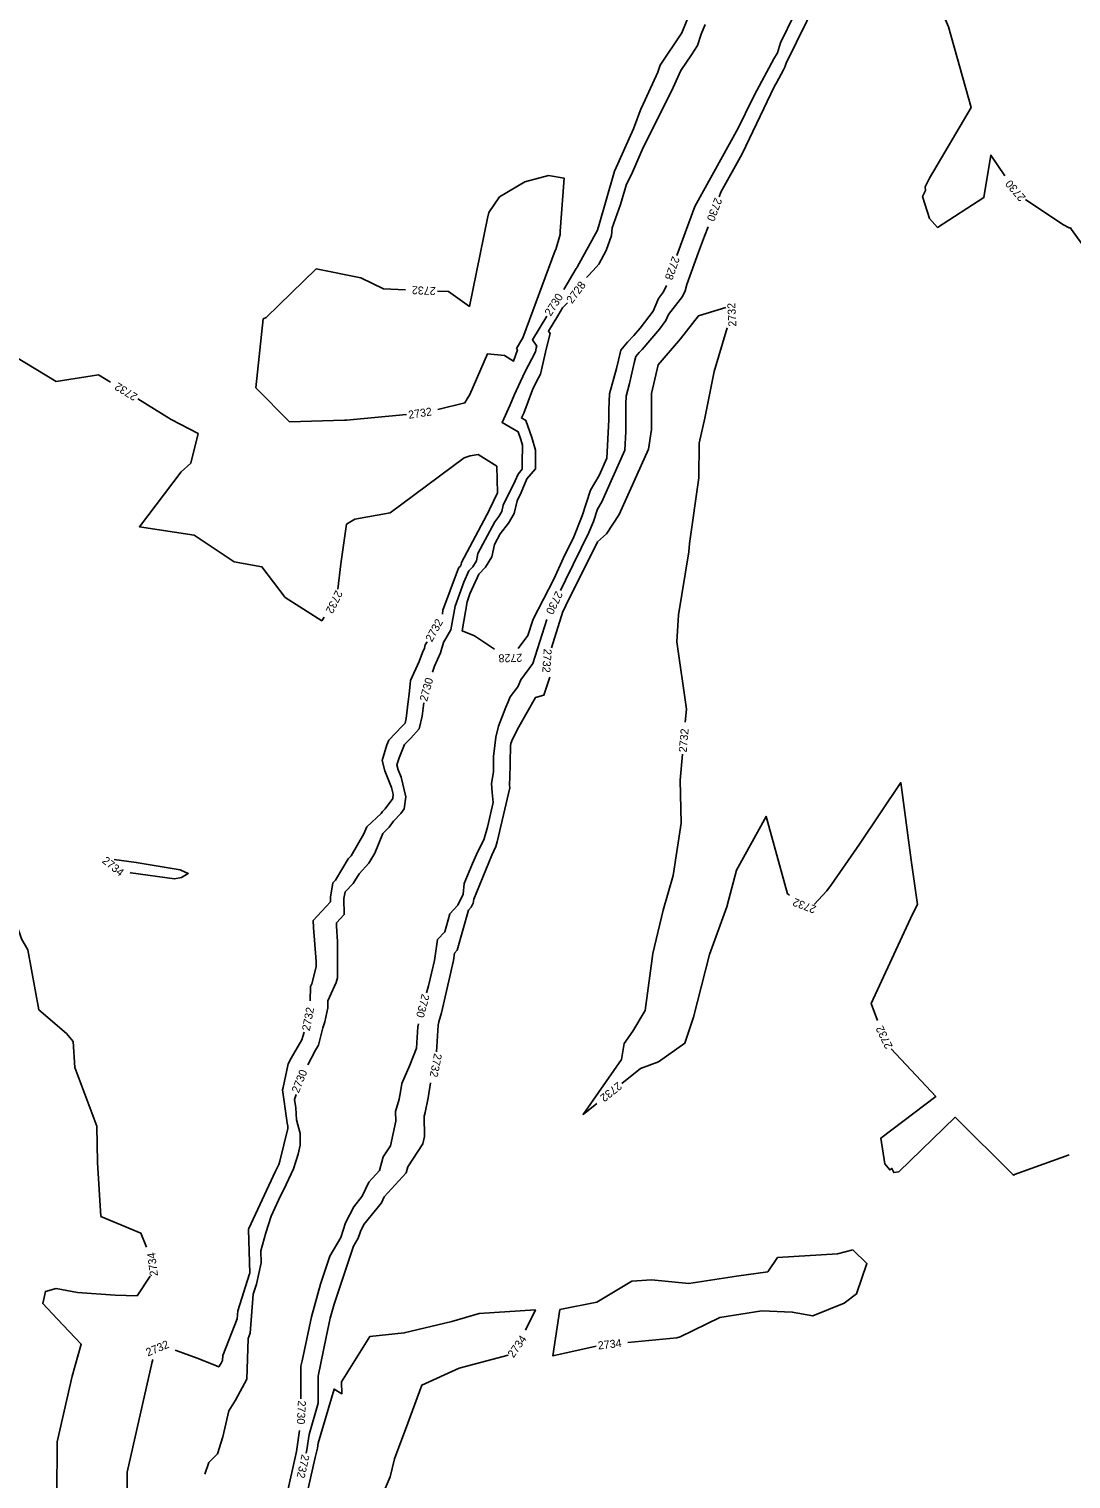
# Model space of a CAD drawing. Extents: x 1326424 to 1329294, y 1001359 to 1003823.
# Drawn here: x 1327730.9 to 1327991.3, y 1002324.7 to 1002687.1 of the extents above; entities that cross this region are included whole.
import ezdxf

# ---------------------------------------------------------------- set-up
doc = ezdxf.new("R2010")
doc.units = 0
doc.layers.add('Scratch_Level_3', color=7, linetype='Continuous')

msp = doc.modelspace()

# ---------------------------------------------------------------- linework, layer by layer
at = {"layer": 'Scratch_Level_3'}
for points in [[(1327903.41, 1002645.16), (1327903.84, 1002646.31), (1327909.12, 1002655.87), (1327917.23, 1002672.75), (1327917.69, 1002673.61), (1327919.45, 1002676.88), (1327919.82, 1002677.51), (1327920.13, 1002678.55), (1327927.88, 1002694.26), (1327928.12, 1002694.72), (1327928.32, 1002695.17), (1327928.5, 1002695.83), (1327928.83, 1002696.22), (1327929.03, 1002696.74), (1327929.28, 1002697.11), (1327935.25, 1002708.97), (1327935.81, 1002709.73), (1327936.52, 1002710.78), (1327944.29, 1002720.67), (1327944.66, 1002721.18), (1327945.02, 1002721.8), (1327952.7, 1002731.65)], [(1327892.8, 1002630.49), (1327895.83, 1002638.63), (1327897.33, 1002642.68), (1327908.14, 1002662.27), (1327911.68, 1002669.62), (1327912.81, 1002671.7), (1327917.06, 1002679.6), (1327917.94, 1002681.14), (1327918.7, 1002683.63), (1327922.13, 1002690.59), (1327923.2, 1002692.59), (1327924.06, 1002694.54), (1327924.85, 1002697.4), (1327926.28, 1002699.1), (1327927.14, 1002701.33), (1327928.21, 1002702.94), (1327930.85, 1002708.19), (1327933.4, 1002711.66), (1327936.64, 1002716.4), (1327938.59, 1002718.88)], [(1327903.99, 1002712.88), (1327899.92, 1002703.62), (1327897.88, 1002701.53), (1327897.29, 1002699.69), (1327896.05, 1002690.99), (1327894.09, 1002686.08), (1327888.66, 1002678.04), (1327888.08, 1002676.28), (1327883.94, 1002667.39), (1327883.9, 1002667.26), (1327881.96, 1002662.16), (1327877.34, 1002651.7), (1327877.25, 1002651.52), (1327873.26, 1002637.63), (1327873.1, 1002637.2), (1327873.09, 1002637.06), (1327872.99, 1002636.78), (1327867.9, 1002627.53), (1327867.8, 1002627.41), (1327867.7, 1002627.31), (1327867.61, 1002627.22), (1327864.57, 1002622)], [(1327960.59, 1002701.1), (1327959.92, 1002695.99), (1327958.88, 1002691.85), (1327960.67, 1002687.57), (1327966.34, 1002667.49), (1327955.96, 1002649.77), (1327954.84, 1002647.61), (1327954.91, 1002646.71), (1327954.23, 1002645.25), (1327955.95, 1002639.71), (1327957.96, 1002637.5), (1327969.57, 1002644.95), (1327971.28, 1002655.57), (1327974.79, 1002650.4)], [(1327899.85, 1002688.2), (1327898.89, 1002685.81), (1327897.96, 1002682.96), (1327896.47, 1002680.65), (1327893.83, 1002676.73), (1327891.85, 1002672.49), (1327884.14, 1002656.84), (1327881.46, 1002650.75), (1327880.22, 1002648.27), (1327878.76, 1002643.18), (1327876.67, 1002637.37), (1327876.48, 1002635.45), (1327875.17, 1002631.69), (1327873.31, 1002628.3), (1327871.9, 1002626.68), (1327870.56, 1002625.32), (1327870.26, 1002625)], [(1327852.71, 1002607.19), (1327854.33, 1002609.86), (1327862.41, 1002631.69), (1327862.54, 1002631.98), (1327863.61, 1002635.75), (1327863.67, 1002636.56), (1327864.64, 1002649.82), (1327860.73, 1002650.44), (1327854.84, 1002648.86), (1327848.47, 1002645.1), (1327845.79, 1002641.22), (1327845.49, 1002639.81), (1327840.95, 1002617.76), (1327835.74, 1002621.44), (1327832.98, 1002621.55)], [(1327979.93, 1002644.44), (1327989.31, 1002638.24), (1327990.88, 1002637.36), (1327991.16, 1002637.37), (1327991.46, 1002636.93), (1328004.81, 1002618.42), (1328010.28, 1002605.68), (1328012.59, 1002600.82), (1328012.55, 1002592.38), (1328012.79, 1002589.75), (1328014.63, 1002572.78), (1328016, 1002557.55), (1328016.15, 1002556.93)], [(1327863.77, 1002546.72), (1327864.98, 1002549.35), (1327870.85, 1002561.22), (1327871.96, 1002563.97), (1327872.97, 1002567.11), (1327874.04, 1002568.89), (1327879.8, 1002581.79), (1327880.03, 1002586.46), (1327880.08, 1002593.44), (1327880.16, 1002595.34), (1327881.01, 1002598.46), (1327882.26, 1002604.02), (1327882.55, 1002605.24), (1327883.37, 1002606.21), (1327884.14, 1002607.01), (1327888.49, 1002612.09), (1327890.05, 1002614.19), (1327890.71, 1002615.73), (1327894.2, 1002620.21), (1327894.85, 1002621.61), (1327895.28, 1002623.19), (1327898.26, 1002631.28), (1327899.74, 1002635.26), (1327900.63, 1002637.66)], [(1327824.99, 1002621.89), (1327819.5, 1002622.13), (1327813.85, 1002624.9), (1327802.67, 1002627.13), (1327790.17, 1002614.94), (1327789.44, 1002614.63), (1327787.59, 1002597.37), (1327795.99, 1002588.94), (1327809.72, 1002589.34), (1327809.99, 1002589.35), (1327810.29, 1002589.28), (1327825.21, 1002590.77)], [(1327853.14, 1002532.24), (1327855.58, 1002535.48), (1327856.86, 1002539.59), (1327862.03, 1002549.55), (1327864.85, 1002555.68), (1327866.86, 1002559.74), (1327869.12, 1002565.38), (1327871.19, 1002571.81), (1327873.38, 1002575.46), (1327875.35, 1002579.86), (1327875.82, 1002589.44), (1327875.84, 1002592), (1327876, 1002595.88), (1327877.74, 1002602.27), (1327878.2, 1002604.31), (1327878.8, 1002606.81), (1327880.48, 1002608.81), (1327882.07, 1002610.44), (1327883.66, 1002612.3), (1327886.86, 1002616.6), (1327888.2, 1002619.76), (1327889.48, 1002621.4), (1327890.2, 1002622.94)], [(1327865.49, 1002618.62), (1327864.26, 1002617.36), (1327863.06, 1002615.42), (1327860.71, 1002611.54), (1327861.11, 1002610.98), (1327860.24, 1002607.43), (1327858.74, 1002600.85), (1327857.77, 1002598.97), (1327856.77, 1002596.88), (1327854.53, 1002591.08), (1327853.97, 1002589.88), (1327855.06, 1002589.25), (1327856.57, 1002585.02), (1327857.48, 1002581.85), (1327857.45, 1002580.34), (1327857.48, 1002577.13), (1327855.33, 1002574.62), (1327853.91, 1002571.23), (1327852.9, 1002569.17), (1327852.16, 1002565.96), (1327850.71, 1002563.57), (1327848.64, 1002560.94), (1327847.2, 1002558.21), (1327846.55, 1002555.19), (1327845.01, 1002552.61), (1327843.34, 1002550.84), (1327841.11, 1002545.93), (1327840.37, 1002543.91), (1327839.13, 1002536.7), (1327842.2, 1002535.44), (1327847.27, 1002532.07)], [(1327905.09, 1002617.49), (1327898.21, 1002615.42), (1327893.71, 1002609.66), (1327888.11, 1002603.12), (1327886.51, 1002595.96), (1327886.45, 1002586.98), (1327885.74, 1002582.1), (1327878.42, 1002565.74), (1327875.24, 1002560.93), (1327872.96, 1002558.88), (1327865.1, 1002543.01), (1327864.83, 1002542.42), (1327864.33, 1002541.47), (1327861.52, 1002532.44)], [(1327705.24, 1002613.88), (1327705.85, 1002607.81), (1327706.06, 1002607.25), (1327706.07, 1002607.15), (1327706.17, 1002606.02), (1327708.22, 1002587.58), (1327708.48, 1002585.12), (1327709.29, 1002585.11), (1327718.49, 1002585.76), (1327717.82, 1002587.72), (1327718.25, 1002590.34), (1327718.81, 1002610.36), (1327737.66, 1002599), (1327748.28, 1002600.67), (1327751.25, 1002598.83)], [(1327860.28, 1002615.27), (1327856.71, 1002609.37), (1327857.8, 1002607.84), (1327857.68, 1002607.34), (1327857.47, 1002606.41), (1327854.84, 1002601.29), (1327852.11, 1002595.58), (1327851.17, 1002593.14), (1327849.15, 1002588.73), (1327853.12, 1002586.44), (1327853.81, 1002584.51), (1327854.23, 1002583.06), (1327854.16, 1002578.63), (1327854.17, 1002577.04), (1327853.11, 1002575.8), (1327852.4, 1002574.12), (1327849.44, 1002568.09), (1327849.07, 1002566.47), (1327848.34, 1002565.27), (1327847.3, 1002563.94), (1327843.1, 1002555.97), (1327842.71, 1002554.2), (1327841.82, 1002552.7), (1327840.84, 1002551.67), (1327839.54, 1002548.8), (1327837.37, 1002542.88), (1327836.35, 1002536.93), (1327834.47, 1002533.8), (1327833.76, 1002531.17), (1327832.25, 1002527.84), (1327831.7, 1002526.34)], [(1327894.91, 1002513.84), (1327895.19, 1002517.14), (1327892.79, 1002533.9), (1327893.2, 1002540.66), (1327895.79, 1002556.45), (1327895.93, 1002558.54), (1327898.27, 1002574.92), (1327898.39, 1002583.56), (1327899.78, 1002589.8), (1327902.1, 1002601.48), (1327905.37, 1002612.4)], [(1327833.11, 1002591.97), (1327839.85, 1002593.62), (1327840.41, 1002594.66), (1327841.06, 1002595.73), (1327845.46, 1002605.86), (1327849.74, 1002605.44), (1327852.01, 1002604.07), (1327852.95, 1002606.86), (1327852.71, 1002607.19)], [(1327758.06, 1002594.63), (1327766.41, 1002589.48), (1327773.2, 1002585.95), (1327771.34, 1002578.6), (1327768.91, 1002576.37), (1327758.49, 1002562.69), (1327772.2, 1002560.61), (1327782.14, 1002553.96), (1327789.1, 1002552.71), (1327794.9, 1002545.03), (1327804.06, 1002539.19), (1327804.67, 1002540.08)], [(1327808.12, 1002547.08), (1327808.82, 1002553.43), (1327810.21, 1002563.31), (1327812.32, 1002564.57), (1327821.18, 1002566.18), (1327839.67, 1002579.91), (1327841.19, 1002580.4), (1327843.12, 1002580.71), (1327847.8, 1002577.81), (1327848.02, 1002571.16), (1327845.99, 1002567.01), (1327845.98, 1002566.99), (1327845.97, 1002566.97), (1327845.95, 1002566.95), (1327838.99, 1002553.72), (1327838.88, 1002553.22), (1327838.62, 1002552.79), (1327838.34, 1002552.5), (1327837.97, 1002551.68), (1327834.36, 1002541.85), (1327834.2, 1002540.87)], [(1327830.27, 1002446.25), (1327830.75, 1002447.96), (1327832.21, 1002454.27), (1327832.98, 1002459.52), (1327834.82, 1002461.42), (1327836.1, 1002465.99), (1327838.05, 1002468.12), (1327839.4, 1002470.9), (1327839.66, 1002473.52), (1327841.74, 1002478.57), (1327843.11, 1002481.57), (1327844.54, 1002484.46), (1327845.47, 1002487.64), (1327846.91, 1002493.8), (1327846.67, 1002496.32), (1327846.45, 1002498.55), (1327846.95, 1002501.45), (1327847.02, 1002505.27), (1327847.32, 1002508.01), (1327847.61, 1002510.13), (1327848.24, 1002512.89), (1327850.03, 1002517.57), (1327850.65, 1002518.91), (1327851.18, 1002520.22), (1327853.05, 1002522.65), (1327853.78, 1002524.42), (1327856.84, 1002528.5), (1327860.29, 1002539.54)], [(1327830.37, 1002533.9), (1327829.95, 1002533.19), (1327829.72, 1002532.34), (1327829.22, 1002531.25), (1327828.42, 1002529.04), (1327826.27, 1002524.23), (1327825.95, 1002520.89), (1327825.64, 1002519.04), (1327825.17, 1002514.74), (1327824.9, 1002513.62), (1327824.18, 1002512.83), (1327820.83, 1002509.38), (1327820.35, 1002508.22), (1327819.13, 1002504.29), (1327819.85, 1002501.68), (1327821.53, 1002497.53), (1327821.93, 1002495.83), (1327821.79, 1002494.8), (1327819.88, 1002492.18), (1327819.26, 1002491.51), (1327818.88, 1002490.99), (1327815.3, 1002487.69), (1327814.61, 1002485.97), (1327811.42, 1002480.49), (1327810.7, 1002479.74), (1327807.46, 1002474.34), (1327806.87, 1002473.73), (1327806.24, 1002470.16), (1327806.27, 1002468.97), (1327801.92, 1002464.28), (1327802, 1002462.53), (1327802.64, 1002454.04), (1327802.63, 1002452.68), (1327801.58, 1002448.49), (1327801.27, 1002447.81), (1327801.14, 1002444.21)], [(1327861.03, 1002525.08), (1327859.53, 1002520.6), (1327857.49, 1002520.02), (1327853.35, 1002512.67), (1327851.76, 1002509.64), (1327851.33, 1002508.5), (1327851.28, 1002508.31), (1327851.27, 1002508.16), (1327851.24, 1002507.97), (1327851.1, 1002499.6), (1327850.96, 1002498.78), (1327851.02, 1002498.15), (1327851.09, 1002497.43), (1327847.93, 1002483.93), (1327847.6, 1002482.79), (1327847.08, 1002481.74), (1327846.59, 1002480.66), (1327842.03, 1002469.59), (1327841.93, 1002468.64), (1327841.44, 1002467.64), (1327840.74, 1002466.87), (1327837.93, 1002456.85), (1327837.27, 1002456.16), (1327836.99, 1002454.26), (1327833.96, 1002441.21), (1327833.33, 1002438.96), (1327833.17, 1002438.17), (1327832.74, 1002431.51)], [(1327829.6, 1002518.65), (1327829.38, 1002517.35), (1327829.17, 1002515.38), (1327828.37, 1002512.16), (1327826.31, 1002509.88), (1327824.78, 1002508.31), (1327823.41, 1002504.96), (1327822.85, 1002503.16), (1327823.17, 1002501.97), (1327823.94, 1002500.08), (1327825.1, 1002495.18), (1327824.7, 1002492.21), (1327823.82, 1002491.01), (1327822.03, 1002489.08), (1327820.95, 1002487.58), (1327819.31, 1002486.07), (1327817.33, 1002481.09), (1327815.87, 1002478.59), (1327813.4, 1002475.99), (1327811.92, 1002473.52), (1327809.89, 1002471.43), (1327809.6, 1002469.8), (1327809.69, 1002465.83), (1327807.71, 1002463.69), (1327807.75, 1002462.89), (1327808.04, 1002459.02), (1327807.99, 1002449.94), (1327807.7, 1002448.79), (1327805.62, 1002444.23), (1327805.56, 1002442.46), (1327804.82, 1002438.98), (1327804.37, 1002437.46), (1327803.22, 1002433.1), (1327802.49, 1002431.85), (1327800.56, 1002428.22)], [(1327872.8, 1002418.58), (1327869.37, 1002415.83), (1327878.97, 1002429.54), (1327879.68, 1002433.58), (1327881.81, 1002436.66), (1327884.87, 1002441.77), (1327886.79, 1002456.04), (1327889.4, 1002466.85), (1327891.87, 1002475.55), (1327893.87, 1002488.62), (1327893.67, 1002499.4), (1327894.22, 1002505.87)], [(1327942.96, 1002439.34), (1327941.35, 1002443.59), (1327951.73, 1002465.86), (1327952.94, 1002468.32), (1327951.4, 1002479.41), (1327948.78, 1002498.75), (1327938.43, 1002483.34), (1327931.45, 1002473.27), (1327930.28, 1002471.68), (1327927.11, 1002468.28)], [(1327920.97, 1002470.59), (1327920.5, 1002470.96), (1327915.12, 1002490.29), (1327907.71, 1002476.88), (1327905.26, 1002467.71), (1327900.98, 1002455.78), (1327896.94, 1002440.1), (1327894.8, 1002433.6), (1327888.23, 1002429.01), (1327883.75, 1002427.35), (1327879.05, 1002423.58)], [(1327769, 1002475.01), (1327770.71, 1002476), (1327768.85, 1002476.9), (1327768.71, 1002476.92), (1327757.69, 1002478.82), (1327752.19, 1002479.55)], [(1327756.22, 1002476.29), (1327756.38, 1002476.24), (1327767.25, 1002474.72), (1327769, 1002475.01)], [(1327725.5, 1002464.22), (1327725.42, 1002460.96), (1327727.79, 1002463.39), (1327728.99, 1002459.75), (1327730.61, 1002456.95), (1327733.35, 1002442), (1327740.27, 1002436.02), (1327741.92, 1002434.08), (1327742.32, 1002427.54), (1327747.82, 1002412.88), (1327748.06, 1002403.86), (1327748.86, 1002390.35), (1327758.85, 1002386.18), (1327760.24, 1002382.64)], [(1327798.87, 1002344.79), (1327798.85, 1002345.98), (1327798.87, 1002352.92), (1327799.15, 1002354.29), (1327801.53, 1002365.25), (1327803.75, 1002373.4), (1327806.09, 1002380.39), (1327808.82, 1002385.07), (1327810.03, 1002388.74), (1327812.07, 1002392.78), (1327814.18, 1002395.4), (1327815.82, 1002398.91), (1327818.47, 1002401.83), (1327819.39, 1002405.21), (1327821.22, 1002407.97), (1327822.57, 1002414.14), (1327822.52, 1002416.6), (1327823.39, 1002419.66), (1327823.74, 1002421.46), (1327824.09, 1002423.6), (1327826.1, 1002428.14), (1327827.75, 1002432.36), (1327828.1, 1002437.74), (1327828.25, 1002438.51)], [(1327799.63, 1002436.41), (1327799.3, 1002435.29), (1327799.09, 1002434.5), (1327796.46, 1002429.93), (1327795.67, 1002428.44), (1327794.46, 1002422.58), (1327794.29, 1002421.94), (1327795.35, 1002414.31), (1327795.39, 1002413.66), (1327795.59, 1002412.93), (1327795.6, 1002412.29), (1327793.6, 1002404.14), (1327793.36, 1002403.35), (1327792.95, 1002402.51), (1327792.54, 1002401.66), (1327785.82, 1002387.31), (1327785.78, 1002387.18), (1327785.75, 1002387.05), (1327786.07, 1002376.18), (1327786.04, 1002376.02), (1327783.11, 1002366.78), (1327782.96, 1002364.78), (1327779.31, 1002355.61), (1327779.27, 1002354.31), (1327778.9, 1002353.64), (1327778.33, 1002352.72), (1327773.15, 1002354.88), (1327767.4, 1002356.89)], [(1327990.86, 1002405.72), (1327977.18, 1002400.82), (1327977.12, 1002400.69), (1327976.87, 1002400.77), (1327962.34, 1002415.11), (1327948.29, 1002401.51), (1327947.02, 1002401.3), (1327946.56, 1002402.36), (1327946.01, 1002401.96), (1327944.77, 1002403.46), (1327943.8, 1002409.94), (1327957.51, 1002420.3), (1327946.4, 1002432.24)], [(1327831.24, 1002423.75), (1327830.64, 1002420.02), (1327829.91, 1002416.29), (1327829.65, 1002415.38), (1327829.76, 1002410.29), (1327829.36, 1002408.45), (1327825.57, 1002402.74), (1327825.17, 1002401.26), (1327819.68, 1002395.21), (1327818.98, 1002393.71), (1327814.6, 1002388.31), (1327813.71, 1002386.55), (1327813.18, 1002384.95), (1327811.99, 1002382.9), (1327807.15, 1002368.43), (1327806.2, 1002364.92), (1327805.17, 1002360.2), (1327803.15, 1002350.45), (1327803.14, 1002347.03), (1327803.2, 1002343.68), (1327800.9, 1002335.89), (1327800.34, 1002332.01), (1327800.16, 1002331.22)], [(1327797.63, 1002420.85), (1327797.28, 1002419.58), (1327797.57, 1002417.49), (1327797.75, 1002414.5), (1327798.66, 1002411.07), (1327798.71, 1002408.14), (1327798.16, 1002405.9), (1327797.03, 1002402.23), (1327795.14, 1002398.32), (1327793.24, 1002394.37), (1327791.4, 1002390.42), (1327790.07, 1002386.24), (1327788.82, 1002381.76), (1327788.91, 1002378.77), (1327787.74, 1002373.44), (1327786.94, 1002370.9), (1327786.21, 1002361.15), (1327785.69, 1002359.85), (1327785.37, 1002349.67), (1327782.49, 1002344.39), (1327780.86, 1002341.77), (1327779.31, 1002335.23), (1327777.99, 1002331), (1327775.85, 1002328.86), (1327774.81, 1002325.96)], [(1327936.82, 1002381.96), (1327932.97, 1002381.02), (1327917.98, 1002380.09), (1327915.51, 1002376.46), (1327907.68, 1002375.42), (1327895.8, 1002373.55), (1327886.49, 1002374.51), (1327881.56, 1002374.14), (1327872.85, 1002368.89), (1327863.59, 1002367.07), (1327861.83, 1002355.5), (1327872.63, 1002357.95)], [(1327880.57, 1002358.86), (1327892.81, 1002360.04), (1327893.64, 1002360.22), (1327903.57, 1002365.07), (1327914.05, 1002366.72), (1327921.64, 1002366.44), (1327926.78, 1002365.47), (1327934.59, 1002368.71), (1327937.72, 1002370.96), (1327940.29, 1002378.56), (1327936.82, 1002381.96)], [(1327761.16, 1002375.41), (1327757.9, 1002370.54), (1327752.42, 1002370.64), (1327743.05, 1002371.31), (1327737.66, 1002372.34), (1327735, 1002371.6), (1327734.32, 1002368.58), (1327737.94, 1002364.75), (1327743.96, 1002358.41), (1327741.68, 1002350.46), (1327737.94, 1002334.03), (1327737.79, 1002307.01), (1327737.34, 1002305.3)], [(1327854.97, 1002361.92), (1327857.48, 1002366.97), (1327843.44, 1002366.06), (1327836.6, 1002364.05), (1327824.7, 1002361.25), (1327816.11, 1002360.36), (1327809, 1002348.99), (1327809.09, 1002346.04), (1327807.13, 1002347.19), (1327803.14, 1002333.72), (1327802.96, 1002332.42), (1327802.44, 1002330.12), (1327798.96, 1002314.57)], [(1327761.86, 1002354.56), (1327761.7, 1002354), (1327755.42, 1002326.4), (1327755.34, 1002311.86), (1327752.38, 1002300.7), (1327754.93, 1002293.85), (1327756.18, 1002291.38), (1327754.77, 1002288.25), (1327759.71, 1002284.2), (1327758.39, 1002282.03), (1327757.76, 1002279.14), (1327757.26, 1002276.24), (1327756.28, 1002267.63), (1327755.7, 1002264.17), (1327754.73, 1002259.77)], [(1327840.73, 1002291.82), (1327839.3, 1002293.69), (1327829.98, 1002300.22), (1327828, 1002298.86), (1327827.71, 1002301.35), (1327813.94, 1002307.92), (1327813.8, 1002308.33), (1327814.06, 1002308.7), (1327821.15, 1002325.29), (1327822.25, 1002329.73), (1327825.57, 1002338.7), (1327829.06, 1002348.17), (1327838.39, 1002352.4), (1327850.65, 1002355.69)], [(1327772.89, 1002318.23), (1327772.88, 1002316.71), (1327768.65, 1002300.72), (1327769.01, 1002299.76), (1327769.92, 1002297.96), (1327777.89, 1002294.14), (1327776.86, 1002291.87), (1327782.86, 1002282.63), (1327786.65, 1002292.41), (1327786.86, 1002293.35), (1327787.18, 1002294.5), (1327794.79, 1002318.5), (1327795.14, 1002320.04), (1327797.72, 1002331.59), (1327798.48, 1002336.85)]]:
    msp.add_lwpolyline(points, dxfattribs=at)

# ---------------------------------------------------------------- texts
for s, rotation, p in [('2730', 130.8072, (1327980.1, 1002645.05)), ('2730', 249.6485, (1327902.32, 1002645.09)), ('2728', 251.0314, (1327891.7, 1002630.43)), ('2732', 177.5624, (1327832.58, 1002622.57)), ('2728', 53.2361, (1327866.62, 1002618.29)), ('2730', 57.5238, (1327861.29, 1002615.15)), ('2732', 93.0951, (1327907.71, 1002612.74)), ('2732', 148.3168, (1327758.2, 1002595.71)), ('2732', 8.6057, (1327825.83, 1002589.65)), ('2732', 243.7963, (1327807.61, 1002547)), ('2730', 244.1494, (1327862.61, 1002546.79)), ('2732', 61.2622, (1327831.6, 1002533.74)), ('2732', 266.2372, (1327859.56, 1002532.24)), ('2728', 181.6395, (1327854.15, 1002530.95)), ('2730', 74.7189, (1327830.38, 1002518.89)), ('2732', 85.0909, (1327895.26, 1002506.23)), ('2734', 321.0208, (1327749, 1002478.92)), ('2732', 159.3138, (1327927.82, 1002467.84)), ('2730', 255.3984, (1327829.11, 1002446.09)), ('2732', 79.0508, (1327801.05, 1002436.57)), ('2732', 115.8236, (1327946.82, 1002432.84)), ('2732', 259.1296, (1327832.16, 1002431.2)), ('2730', 68.2616, (1327798.3, 1002421.02)), ('2732', 218.7056, (1327878.07, 1002424.08)), ('2734', 97.259, (1327763.14, 1002375.52)), ('2732', 22.828, (1327760.62, 1002355.33)), ('2734', 55.2948, (1327851.99, 1002354.85)), ('2734', 6.583, (1327873.18, 1002357.08)), ('2730', 267.1698, (1327798.12, 1002344.39)), ('2732', 257.3782, (1327799.09, 1002331))]:
    msp.add_text(s, height=2, rotation=rotation, dxfattribs=at).set_placement(p)

doc.saveas('drawing.dxf')
